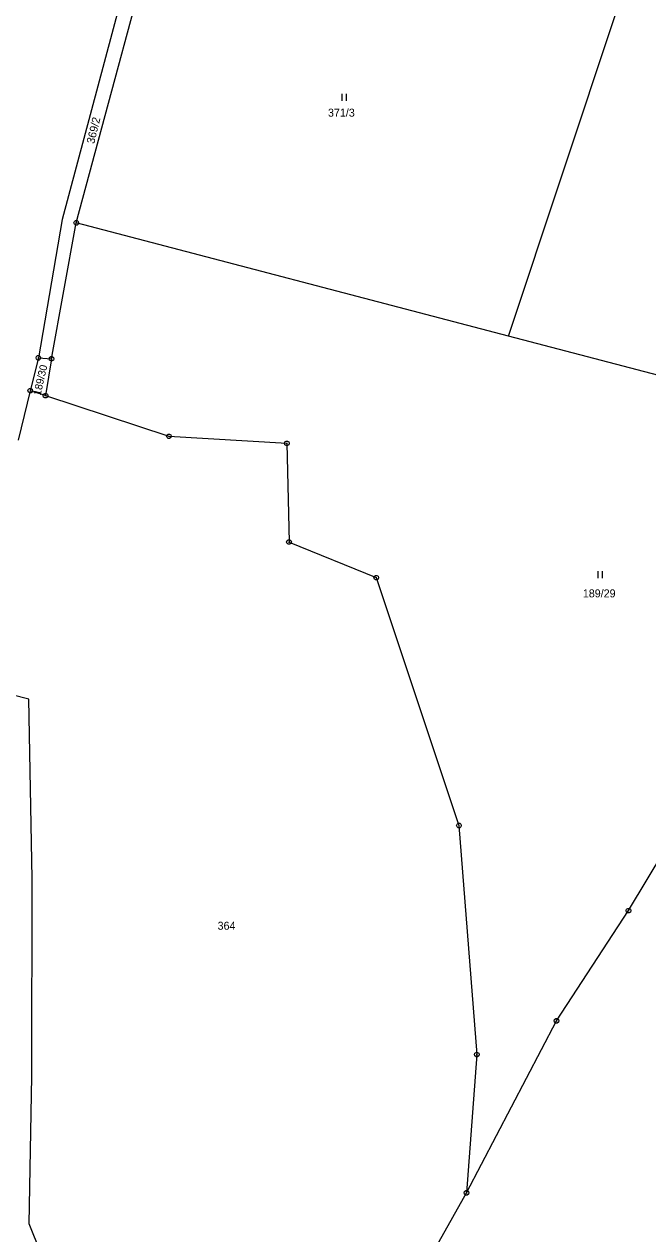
# Model space of a CAD drawing. Extents: x -694465 to -690527, y -983694 to -978978.
# Drawn here: x -693351.2 to -693218.8, y -980627.2 to -980370.2 of the extents above; entities that cross this region are included whole.
import ezdxf

# ---------------------------------------------------------------- set-up
doc = ezdxf.new("R2010")
doc.units = 0
for name, color, linetype in [('Vrstva 1', 7, 'Continuous'), ('Vrstva 18', 7, 'Continuous'), ('Vrstva 24', 7, 'Continuous'), ('Vrstva 25', 7, 'Continuous')]:
    doc.layers.add(name, color=color, linetype=linetype)

msp = doc.modelspace()

# ---------------------------------------------------------------- linework, layer by layer
at = {"layer": 'Vrstva 1'}
for points in [[(-693323.39, -980337.74), (-693343.13, -980411.7)], [(-693340.1, -980412.39), (-693320.21, -980338.67)], [(-693248.34, -980436.49), (-693225.4, -980367.45)], [(-693343.13, -980411.7), (-693348.15, -980441.05)], [(-693345.36, -980441.25), (-693340.1, -980412.39)], [(-693248.34, -980436.49), (-693340.1, -980412.39)], [(-693204.23, -980448), (-693248.34, -980436.49)], [(-693348.15, -980441.05), (-693349.87, -980448.04)], [(-693348.15, -980441.05), (-693345.36, -980441.25)], [(-693345.36, -980441.25), (-693346.65, -980449.1)], [(-693349.87, -980448.04), (-693352.45, -980458.55)], [(-693346.65, -980449.1), (-693349.87, -980448.04)], [(-693346.65, -980449.1), (-693320.44, -980457.73)], [(-693320.44, -980457.73), (-693295.41, -980459.22)], [(-693295.41, -980459.22), (-693294.94, -980480.2)], [(-693294.94, -980480.2), (-693276.42, -980487.77)], [(-693276.42, -980487.77), (-693258.86, -980540.44)], [(-693350.19, -980513.62), (-693361.34, -980510.72)], [(-693349.44, -980551.69), (-693350.19, -980513.62)], [(-693222.87, -980558.52), (-693195.97, -980513.8)], [(-693258.86, -980540.44), (-693255.07, -980589.11)], [(-693349.55, -980593.74), (-693349.44, -980551.69)], [(-693238.14, -980581.93), (-693222.87, -980558.52)], [(-693257.27, -980618.48), (-693238.14, -980581.93)], [(-693255.07, -980589.11), (-693257.27, -980618.48)], [(-693350.13, -980625.08), (-693349.55, -980593.74)], [(-693272.39, -980645.43), (-693257.27, -980618.48)], [(-693315.43, -980711.35), (-693350.13, -980625.08)]]:
    msp.add_lwpolyline(points, dxfattribs=at)
at = {"layer": 'Vrstva 24'}
for points in [[(-693339.946, -980411.914), (-693339.696, -980412.096), (-693339.6, -980412.39), (-693339.696, -980412.684), (-693339.946, -980412.866), (-693340.254, -980412.866), (-693340.504, -980412.684), (-693340.6, -980412.39), (-693340.504, -980412.096), (-693340.254, -980411.914)], [(-693347.996, -980440.574), (-693347.746, -980440.756), (-693347.65, -980441.05), (-693347.746, -980441.344), (-693347.996, -980441.526), (-693348.304, -980441.526), (-693348.554, -980441.344), (-693348.65, -980441.05), (-693348.554, -980440.756), (-693348.304, -980440.574)], [(-693345.206, -980440.774), (-693344.956, -980440.956), (-693344.86, -980441.25), (-693344.956, -980441.544), (-693345.206, -980441.726), (-693345.514, -980441.726), (-693345.764, -980441.544), (-693345.86, -980441.25), (-693345.764, -980440.956), (-693345.514, -980440.774)], [(-693349.716, -980447.564), (-693349.466, -980447.746), (-693349.37, -980448.04), (-693349.466, -980448.334), (-693349.716, -980448.516), (-693350.024, -980448.516), (-693350.274, -980448.334), (-693350.37, -980448.04), (-693350.274, -980447.746), (-693350.024, -980447.564)], [(-693346.496, -980448.624), (-693346.246, -980448.806), (-693346.15, -980449.1), (-693346.246, -980449.394), (-693346.496, -980449.576), (-693346.804, -980449.576), (-693347.054, -980449.394), (-693347.15, -980449.1), (-693347.054, -980448.806), (-693346.804, -980448.624)], [(-693320.286, -980457.254), (-693320.036, -980457.436), (-693319.94, -980457.73), (-693320.036, -980458.024), (-693320.286, -980458.206), (-693320.594, -980458.206), (-693320.844, -980458.024), (-693320.94, -980457.73), (-693320.844, -980457.436), (-693320.594, -980457.254)], [(-693295.256, -980458.744), (-693295.006, -980458.926), (-693294.91, -980459.22), (-693295.006, -980459.514), (-693295.256, -980459.696), (-693295.564, -980459.696), (-693295.814, -980459.514), (-693295.91, -980459.22), (-693295.814, -980458.926), (-693295.564, -980458.744)], [(-693294.786, -980479.724), (-693294.536, -980479.906), (-693294.44, -980480.2), (-693294.536, -980480.494), (-693294.786, -980480.676), (-693295.094, -980480.676), (-693295.344, -980480.494), (-693295.44, -980480.2), (-693295.344, -980479.906), (-693295.094, -980479.724)], [(-693276.266, -980487.294), (-693276.016, -980487.476), (-693275.92, -980487.77), (-693276.016, -980488.064), (-693276.266, -980488.246), (-693276.574, -980488.246), (-693276.824, -980488.064), (-693276.92, -980487.77), (-693276.824, -980487.476), (-693276.574, -980487.294)], [(-693258.706, -980539.964), (-693258.456, -980540.146), (-693258.36, -980540.44), (-693258.456, -980540.734), (-693258.706, -980540.916), (-693259.014, -980540.916), (-693259.264, -980540.734), (-693259.36, -980540.44), (-693259.264, -980540.146), (-693259.014, -980539.964)], [(-693222.716, -980558.044), (-693222.466, -980558.226), (-693222.37, -980558.52), (-693222.466, -980558.814), (-693222.716, -980558.996), (-693223.024, -980558.996), (-693223.274, -980558.814), (-693223.37, -980558.52), (-693223.274, -980558.226), (-693223.024, -980558.044)], [(-693237.986, -980581.454), (-693237.736, -980581.636), (-693237.64, -980581.93), (-693237.736, -980582.224), (-693237.986, -980582.406), (-693238.294, -980582.406), (-693238.544, -980582.224), (-693238.64, -980581.93), (-693238.544, -980581.636), (-693238.294, -980581.454)], [(-693254.916, -980588.634), (-693254.666, -980588.816), (-693254.57, -980589.11), (-693254.666, -980589.404), (-693254.916, -980589.586), (-693255.224, -980589.586), (-693255.474, -980589.404), (-693255.57, -980589.11), (-693255.474, -980588.816), (-693255.224, -980588.634)], [(-693257.116, -980618.004), (-693256.866, -980618.186), (-693256.77, -980618.48), (-693256.866, -980618.774), (-693257.116, -980618.956), (-693257.424, -980618.956), (-693257.674, -980618.774), (-693257.77, -980618.48), (-693257.674, -980618.186), (-693257.424, -980618.004)], [(-693257.116, -980618.004), (-693256.866, -980618.186), (-693256.77, -980618.48), (-693256.866, -980618.774), (-693257.116, -980618.956), (-693257.424, -980618.956), (-693257.674, -980618.774), (-693257.77, -980618.48), (-693257.674, -980618.186), (-693257.424, -980618.004)]]:
    msp.add_lwpolyline(points, close=True, dxfattribs=at)
for points in [[(-693340.219, -980412.39), (-693339.98, -980412.39)], [(-693348.269, -980441.05), (-693348.03, -980441.05)], [(-693345.479, -980441.25), (-693345.24, -980441.25)], [(-693349.989, -980448.04), (-693349.75, -980448.04)], [(-693346.769, -980449.1), (-693346.53, -980449.1)], [(-693320.559, -980457.73), (-693320.32, -980457.73)], [(-693295.529, -980459.22), (-693295.29, -980459.22)], [(-693295.059, -980480.2), (-693294.82, -980480.2)], [(-693276.539, -980487.77), (-693276.3, -980487.77)], [(-693258.979, -980540.44), (-693258.74, -980540.44)], [(-693222.989, -980558.52), (-693222.75, -980558.52)], [(-693238.259, -980581.93), (-693238.02, -980581.93)], [(-693255.189, -980589.11), (-693254.95, -980589.11)], [(-693257.389, -980618.48), (-693257.15, -980618.48)], [(-693257.389, -980618.48), (-693257.15, -980618.48)]]:
    msp.add_lwpolyline(points, dxfattribs=at)
at = {"layer": 'Vrstva 25'}
for points in [[(-693283.71, -980384.95), (-693283.71, -980386.45)], [(-693282.71, -980386.45), (-693282.71, -980384.95)], [(-693229.38, -980486.39), (-693229.38, -980487.89)], [(-693228.38, -980487.89), (-693228.38, -980486.39)]]:
    msp.add_lwpolyline(points, dxfattribs=at)

# ---------------------------------------------------------------- texts
at = {"layer": 'Vrstva 18'}
for s, p in [('371/3', (-693286.669, -980389.82)), ('189/29', (-693232.557, -980491.96)), ('364', (-693310.103, -980562.58))]:
    msp.add_text(s, height=1.7, dxfattribs=at).set_placement(p)
for s, height, rotation, p in [('369/2', 1.7, 76.48987, (-693336.3, -980395.694)), ('189/30', 1.6, 77.06282, (-693347.693, -980449.134))]:
    msp.add_text(s, height=height, rotation=rotation, dxfattribs=at).set_placement(p)

doc.saveas('drawing.dxf')
